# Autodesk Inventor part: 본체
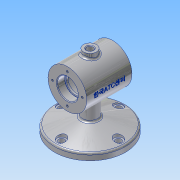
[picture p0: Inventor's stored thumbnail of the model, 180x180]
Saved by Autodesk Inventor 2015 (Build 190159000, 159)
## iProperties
Created: 2018-12
Part Number: 본체
Material: 알루미늄 6061
Document SubType Name: Modeling
Designer: user
Density: 2.7 g/cm^3
Appearance: 알루미늄 - 평지
Mass: 662.307 g
Surface Area: 550.988 cm^2
Volume: 245.299 cm^3
Author: user
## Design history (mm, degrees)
sketch "스케치1"
  geometry: C1 r 55 at (0, 0); 1 further point
  constraints: 1 centre point, 1 coincident
  dimensions: "d0" = 110 diameter of C1
extrude "돌출1" new body sketch "스케치1" distance "d1" = 10; taper "d2" = 0 deg
sketch "스케치2"
  geometry: L1 (-10, 55)-(-10, -55) reference; L2 (-10, -55)-(-24.737, 0); L3 (-10, 0)-(-24.737, 0); L4 (-10, -55)-(-10, 0); 1 further point
  constraints: 6 end point, 1 collinear, 1 horizontal, 1 midpoint
  dimensions: "d3" = 15 deg angle of L1 L2
revolve "회전1" sketch "스케치2" stored, may be unused: angle "d4" = 90 deg
sketch "스케치3"
  geometry: C1 r 4.5 at (44, 0); 1 further point
  constraints: 1 centre point, 1 horizontal alignment
  dimensions: "d5" = 9 diameter of C1; "d6" = 44 distance of C1.centre point (0, 0)
extrude "돌출2" cut sketch "스케치3" distance "d7" = 10; taper "d8" = 0 deg
sketch "스케치4"
  geometry: C1 r 4.5 at (0, 0) reference; C2 r 7 at (0, 0); 1 further point
  constraints: 1 centre point, 1 coincident
  dimensions: "d9" = 14 diameter of C2
extrude "돌출3" cut sketch "스케치4" stored distance "d10" = 10; taper "d11" = 0 deg
sketch "스케치5"
  geometry: C1 r 30 at (0, -75); 1 further point
  constraints: 1 centre point, 1 vertical alignment
  dimensions: "d15" = 75 distance of point (0, 0) C1.centre; "d16" = 60 diameter of C1
extrude "돌출4" join sketch "스케치5" stored distance "d17" = 70; taper "d18" = 0 deg
sketch "스케치6"
  geometry: L1 (-105, -35)-(-45, -35) reference; L2 (-45, 35)-(-105, 35) reference; L3 (-75, -35)-(-75, 35); L4 (-91, -35)-(-91, -23); L5 (-91, -23)-(-89, -23); L6 (-89, -23)-(-89, -20); L7 (-89, -20)-(-100, -20); L8 (-100, -20)-(-100, 20); L9 (-100, 20)-(-89, 20); L10 (-89, 20)-(-89, 23); L11 (-89, 23)-(-91, 23); L12 (-91, 23)-(-91, 35); L13 (-91, -35)-(-75, -35); L14 (-91, 35)-(-75, 35); 1 further point
  constraints: 24 end point, 8 perpendicular, 4 point on line, 2 midpoint, 2 vertical, 1 collinear, 1 horizontal
  dimensions: "d19" = 75 horizontal distance of point (0, 0) L3.end; "d20" = 32 diameter of L4 L3; "d21" = 28 diameter of L6 L3; "d22" = 50 diameter of L8 L3; "d23" = 12 distance of L4.start L4.end; "d24" = 40 distance of L7.end L8.end; "d25" = 3 distance of L5.end L6.end; "d26" = 3 distance of L9.end L10.end; "d27" = 12 distance of L11.end L12.end (derived)
revolve "회전2" sketch "스케치6" stored, may be unused: angle "d28" = 90 deg
chamfer "모따기1" distance "d29" = 1; stored, may be unused: second distance "d30" = 2, angle "d31" = 45 deg
fillet "모깎기1" dims "d32" = 0.3
fillet "모깎기2" dims "d33" = 3
sketch "스케치7"
  geometry: C1 r 12 at (0, 0); 1 further point
  constraints: 1 centre point, 1 coincident
  dimensions: "d34" = 24 diameter of C1
extrude "돌출5" join sketch "스케치7" stored distance "d35" = 70; taper "d36" = 0 deg
sketch "스케치8"
  geometry: C1 r 30 at (0, 0) reference; 2 further points
  constraints: 1 vertical alignment
  dimensions: "d37" = 23 distance of point (0, -23) C1.centre
hole "구멍1" sketch "스케치8" at (0, -23) diameter "d38" = 3.242; stored, may be unused: countersink angle "d42" = 90 deg, drill point angle "d44" = 118 deg; dims "d39" = 8, "d40" = 4, "d41" = 2, "d43" = 10
node "작업 평면1"
sketch "스케치9"
  geometry: C1 r 10 at (0, 0); 1 further point
  constraints: 1 centre point, 1 coincident
  dimensions: "d49" = 20 diameter of C1
extrude "돌출6" join sketch "스케치9" stored distance "d50" = 70; taper "d51" = 0 deg
hole "구멍2" diameter "d54" = 10; stored, may be unused: countersink angle "d58" = 90 deg, drill point angle "d60" = 118 deg; dims "d52" = 10, "d53" = 10, "d55" = 8, "d56" = 4, "d57" = 2, "d59" = 25
chamfer "모따기2" distance "d61" = 1; stored, may be unused: second distance "d62" = 2, angle "d63" = 45 deg
fillet "모깎기3" dims "d64" = 3
fillet "모깎기4" dims "d65" = 3
fillet "모깎기5" dims "d66" = 3
fillet "모깎기6" dims "d67" = 3
node "작업 평면2"
sketch "스케치10"
  geometry: L1 (-105, -35)-(-105, 35) reference; L2 (-105, -35)-(-45, -35) reference; 2 further points
  constraints: 1 other
  dimensions: "d69" = 30 distance from line of point (-75, 0) L1; "d70" = 35 distance from line of point (-75, 0) L2
feature "엠보싱1" sketch "스케치10" dims "d1" = 10, "d2" = 0, "d71" = 0.5, "d72" = 0
node "솔리드1"
pattern_circular "원형 패턴1" dims angle "d13" = 360 deg
pattern_circular "원형 패턴2" dims angle "d46" = 360 deg
mirror "대칭1"
other parameters: "d48" = -112, "d68" = 102
